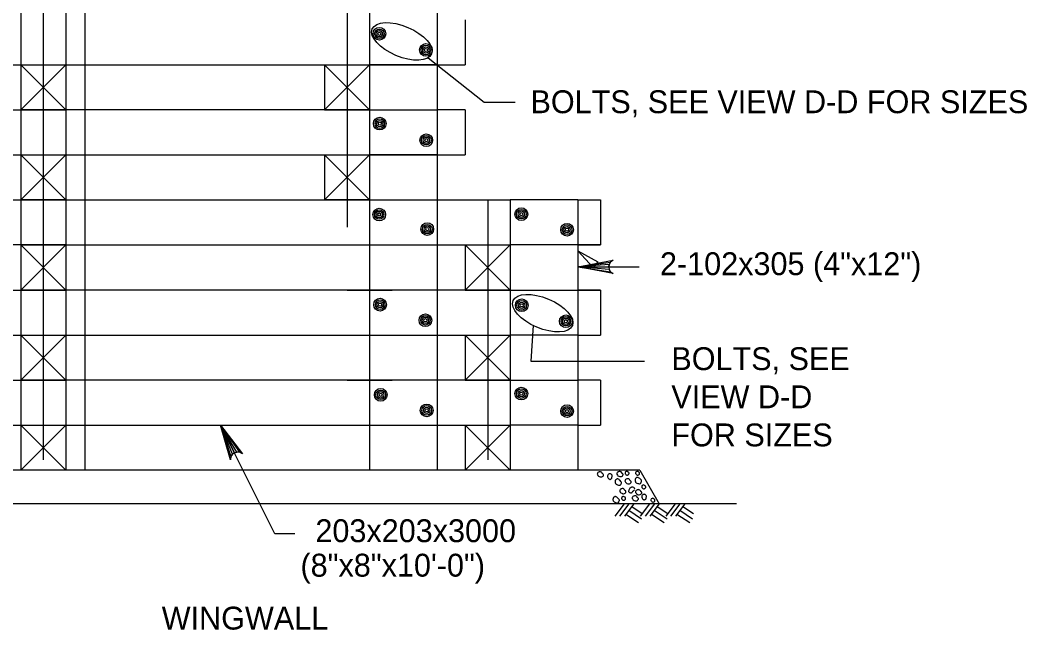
# Model space of a CAD drawing. Extents: x 638142 to 639291, y 297247 to 298438.
# Drawn here: x 638906.2 to 639038.3, y 297993.3 to 298073.2 of the extents above; entities that cross this region are included whole.
import ezdxf

# ---------------------------------------------------------------- set-up
doc = ezdxf.new("R2010")
doc.units = 0
doc.layers.add('3', color=7, linetype='Continuous')
doc.layers.add('5', color=7, linetype='Continuous')

msp = doc.modelspace()

# ---------------------------------------------------------------- linework, layer by layer
at = {"layer": '3'}
for p, q in [((638909.25, 298091), (638909.25, 298015.59)), ((638912.21, 298091), (638912.21, 298014.22)), ((638914.72, 298091), (638914.72, 298025.25)), ((638906.3, 298085.09), (638906.3, 298014.22)), ((638949.12, 298085.09), (638949.12, 298046.07)), ((638952.07, 298085.09), (638952.07, 298025.11)), ((638960.93, 298085.09), (638960.93, 298043.75)), ((638960.93, 298079.18), (638960.93, 298014.22)), ((638964.62, 298073.28), (638964.62, 298067.37)), ((638897.44, 298067.37), (638906.3, 298067.37)), ((638906.3, 298067.37), (638952.07, 298067.37)), ((638906.3, 298067.37), (638912.21, 298067.37)), ((638906.3, 298067.37), (638906.3, 298061.47)), ((638906.3, 298061.47), (638912.21, 298067.37)), ((638906.3, 298067.37), (638912.21, 298061.47)), ((638912.21, 298067.37), (638912.21, 298061.47)), ((638946.16, 298067.37), (638952.07, 298067.37)), ((638946.16, 298067.37), (638952.07, 298061.47)), ((638946.16, 298061.47), (638952.07, 298067.37)), ((638946.16, 298067.37), (638946.16, 298061.47)), ((638952.07, 298067.37), (638960.93, 298067.37)), ((638952.07, 298067.37), (638952.07, 298061.47)), ((638960.93, 298067.37), (638952.07, 298067.37)), ((638960.93, 298067.37), (638964.62, 298067.37)), ((638897.44, 298061.47), (638906.3, 298061.47)), ((638906.3, 298061.47), (638912.21, 298061.47)), ((638912.21, 298061.47), (638906.3, 298061.47)), ((638952.07, 298061.47), (638906.3, 298061.47)), ((638946.16, 298061.47), (638952.07, 298061.47)), ((638952.07, 298061.47), (638960.93, 298061.47)), ((638964.62, 298061.47), (638960.93, 298061.47)), ((638964.62, 298061.47), (638964.62, 298055.56)), ((638897.44, 298055.56), (638906.3, 298055.56)), ((638906.3, 298055.56), (638952.07, 298055.56)), ((638906.3, 298055.56), (638912.21, 298055.56)), ((638906.3, 298055.56), (638912.21, 298049.65)), ((638906.3, 298049.65), (638912.21, 298055.56)), ((638906.3, 298055.56), (638906.3, 298049.65)), ((638912.21, 298055.56), (638912.21, 298049.65)), ((638946.16, 298055.56), (638952.07, 298055.56)), ((638946.16, 298055.56), (638946.16, 298049.65)), ((638946.16, 298049.65), (638952.07, 298055.56)), ((638946.16, 298055.56), (638952.07, 298049.65)), ((638952.07, 298055.56), (638952.07, 298049.65)), ((638952.07, 298055.56), (638960.93, 298055.56)), ((638960.93, 298055.56), (638952.07, 298055.56)), ((638960.93, 298055.56), (638964.62, 298055.56)), ((638897.44, 298049.65), (638906.3, 298049.65)), ((638906.3, 298049.65), (638970.52, 298049.65)), ((638912.21, 298049.65), (638906.3, 298049.65)), ((638906.3, 298049.65), (638912.21, 298049.65)), ((638946.16, 298049.65), (638952.07, 298049.65)), ((638952.07, 298049.65), (638946.16, 298049.65)), ((638967.57, 298049.65), (638967.57, 298015.59)), ((638970.52, 298049.65), (638970.52, 298014.22)), ((638979.38, 298049.65), (638970.52, 298049.65)), ((638979.38, 298049.65), (638979.38, 298014.22)), ((638979.38, 298049.65), (638982.34, 298049.65)), ((638982.34, 298049.65), (638982.34, 298043.75)), ((638912.21, 298043.75), (638897.44, 298043.75)), ((638906.3, 298043.75), (638912.21, 298043.75)), ((638906.3, 298043.75), (638906.3, 298037.84)), ((638906.3, 298037.84), (638912.21, 298043.75)), ((638906.3, 298043.75), (638912.21, 298037.84)), ((638912.21, 298043.75), (638912.21, 298037.84)), ((638912.21, 298043.75), (638970.52, 298043.75)), ((638949.12, 298043.75), (638955.02, 298043.75)), ((638964.62, 298043.75), (638964.62, 298037.84)), ((638964.62, 298037.84), (638970.52, 298043.75)), ((638964.62, 298043.75), (638970.52, 298037.84)), ((638964.62, 298043.75), (638970.52, 298043.75)), ((638970.52, 298043.75), (638970.52, 298037.84)), ((638979.38, 298043.75), (638970.52, 298043.75)), ((638982.34, 298043.75), (638978.64, 298043.75)), ((638979.38, 298043.75), (638982.34, 298043.75)), ((638897.44, 298037.84), (638906.3, 298037.84)), ((638906.3, 298037.84), (638912.21, 298037.84)), ((638970.52, 298037.84), (638906.3, 298037.84)), ((638949.12, 298037.84), (638955.02, 298037.84)), ((638964.62, 298037.84), (638970.52, 298037.84)), ((638970.52, 298037.84), (638979.38, 298037.84)), ((638978.64, 298037.84), (638982.34, 298037.84)), ((638982.34, 298037.84), (638979.38, 298037.84)), ((638982.34, 298037.84), (638982.34, 298031.94)), ((638897.44, 298031.94), (638906.3, 298031.94)), ((638906.3, 298031.94), (638912.21, 298031.94)), ((638906.3, 298031.94), (638912.21, 298026.03)), ((638906.3, 298026.03), (638912.21, 298031.94)), ((638906.3, 298031.94), (638906.3, 298026.03)), ((638906.3, 298031.94), (638970.52, 298031.94)), ((638912.21, 298031.94), (638912.21, 298026.03)), ((638949.12, 298031.94), (638952.07, 298031.94)), ((638964.62, 298031.94), (638970.52, 298031.94)), ((638964.62, 298031.94), (638970.52, 298026.03)), ((638964.62, 298026.03), (638970.52, 298031.94)), ((638964.62, 298031.94), (638964.62, 298026.03)), ((638970.52, 298031.94), (638970.52, 298026.03)), ((638979.38, 298031.94), (638970.52, 298031.94)), ((638979.38, 298031.94), (638982.34, 298031.94)), ((638897.44, 298026.03), (638906.3, 298026.03)), ((638906.3, 298026.03), (638912.21, 298026.03)), ((638970.52, 298026.03), (638906.3, 298026.03)), ((638914.72, 298025.25), (638914.72, 298014.22)), ((638949.12, 298026.03), (638955.02, 298026.03)), ((638952.07, 298025.11), (638952.07, 298014.22)), ((638964.62, 298026.03), (638970.52, 298026.03)), ((638970.52, 298026.03), (638979.38, 298026.03)), ((638982.34, 298026.03), (638979.38, 298026.03)), ((638982.34, 298026.03), (638982.34, 298020.13)), ((638897.44, 298020.13), (638906.3, 298020.13)), ((638906.3, 298020.13), (638912.21, 298020.13)), ((638906.3, 298020.13), (638970.52, 298020.13)), ((638906.3, 298020.13), (638906.3, 298014.22)), ((638906.3, 298014.22), (638912.21, 298020.13)), ((638906.3, 298020.13), (638912.21, 298014.22)), ((638912.21, 298020.13), (638912.21, 298014.22)), ((638920.32, 298020.13), (638968.31, 298020.13)), ((638964.62, 298020.13), (638964.62, 298014.22)), ((638964.62, 298014.22), (638970.52, 298020.13)), ((638964.62, 298020.13), (638970.52, 298014.22)), ((638964.62, 298020.13), (638970.52, 298020.13)), ((638970.52, 298020.13), (638970.52, 298014.22)), ((638979.38, 298020.13), (638970.52, 298020.13)), ((638979.38, 298020.13), (638982.34, 298020.13)), ((638987.5, 298014.22), (638888.58, 298014.22)), ((638987.5, 298014.22), (638990.06, 298009.79)), ((639000.21, 298009.79), (638874.92, 298009.79)), ((638985.45, 298009.79), (638984.23, 298008.2)), ((638986.08, 298009.79), (638984.86, 298008.2)), ((638986.71, 298009.79), (638985.49, 298008.2)), ((638986.07, 298008.96), (638987.75, 298007.86)), ((638986.46, 298009.46), (638987.84, 298008.54)), ((638988.8, 298009.79), (638987.58, 298008.2)), ((638989.43, 298009.79), (638988.21, 298008.2)), ((638990.06, 298009.79), (638988.84, 298008.2)), ((638989.42, 298008.96), (638991.09, 298007.86)), ((638989.8, 298009.46), (638991.19, 298008.54)), ((638992.15, 298009.79), (638990.93, 298008.2)), ((638992.78, 298009.79), (638991.56, 298008.2)), ((638993.41, 298009.79), (638992.19, 298008.2)), ((638992.77, 298008.96), (638994.44, 298007.86)), ((638993.15, 298009.46), (638994.54, 298008.54)), ((638985.69, 298008.45), (638987.36, 298007.35)), ((638989.04, 298008.45), (638990.71, 298007.35)), ((638992.38, 298008.45), (638994.06, 298007.35))]:
    msp.add_line(p, q, dxfattribs=at)
for centre, radius in [((638953.35, 298071.44), 0.833), ((638953.35, 298071.44), 0.625), ((638953.35, 298071.44), 0.417), ((638953.35, 298071.44), 0.208), ((638959.45, 298069.32), 0.833), ((638959.45, 298069.32), 0.625), ((638959.45, 298069.32), 0.417), ((638959.45, 298069.32), 0.208), ((638953.4, 298059.66), 0.833), ((638953.4, 298059.66), 0.625), ((638953.4, 298059.66), 0.417), ((638953.4, 298059.66), 0.208), ((638959.5, 298057.49), 0.833), ((638959.5, 298057.49), 0.625), ((638959.5, 298057.49), 0.417), ((638959.5, 298057.49), 0.208), ((638953.32, 298047.74), 0.833), ((638971.97, 298047.79), 0.833), ((638953.32, 298047.74), 0.625), ((638953.32, 298047.74), 0.417), ((638953.32, 298047.74), 0.208), ((638971.97, 298047.79), 0.625), ((638971.97, 298047.79), 0.417), ((638971.97, 298047.79), 0.208), ((638959.63, 298045.83), 0.833), ((638959.63, 298045.83), 0.625), ((638959.63, 298045.83), 0.417), ((638959.63, 298045.83), 0.208), ((638977.97, 298045.75), 0.833), ((638977.97, 298045.75), 0.625), ((638977.97, 298045.75), 0.417), ((638977.97, 298045.75), 0.208), ((638953.44, 298035.92), 0.833), ((638972.02, 298035.84), 0.833), ((638953.44, 298035.92), 0.625), ((638953.44, 298035.92), 0.417), ((638953.44, 298035.92), 0.208), ((638972.02, 298035.84), 0.625), ((638972.02, 298035.84), 0.417), ((638972.02, 298035.84), 0.208), ((638959.39, 298033.88), 0.833), ((638959.39, 298033.88), 0.625), ((638959.39, 298033.88), 0.417), ((638959.39, 298033.88), 0.208), ((638977.81, 298033.75), 0.833), ((638977.81, 298033.75), 0.625), ((638977.81, 298033.75), 0.417), ((638977.81, 298033.75), 0.208), ((638953.52, 298024.1), 0.833), ((638971.97, 298024.26), 0.833), ((638971.97, 298024.26), 0.625), ((638953.52, 298024.1), 0.625), ((638953.52, 298024.1), 0.417), ((638953.52, 298024.1), 0.208), ((638971.97, 298024.26), 0.417), ((638971.97, 298024.26), 0.208), ((638959.55, 298022.06), 0.833), ((638959.55, 298022.06), 0.625), ((638959.55, 298022.06), 0.417), ((638959.55, 298022.06), 0.208), ((638977.97, 298021.96), 0.833), ((638977.97, 298021.96), 0.625), ((638977.97, 298021.96), 0.417), ((638977.97, 298021.96), 0.208)]:
    msp.add_circle(centre, radius, dxfattribs=at)
for centre, radius, start, end in [((638982.12, 298013.72), 0.185, 160.92, 203.6312), ((638982.22, 298013.68), 0.289, 132.2712, 160.92), ((638982.45, 298013.86), 0.547, 203.6312, 228.0682), ((638982.28, 298013.61), 0.383, 107.4489, 132.2712), ((638982.43, 298013.83), 0.508, 228.0682, 257.7363), ((638982.3, 298013.55), 0.454, 90, 107.449), ((638982.3, 298013.61), 0.387, 71.0851, 90), ((638982.4, 298013.73), 0.402, 257.7363, 291.1829), ((638982.35, 298013.75), 0.246, 39.2919, 71.0851), ((638982.27, 298013.68), 0.35, 12.7289, 39.2919), ((638982.39, 298013.76), 0.433, 291.1829, 314.9975), ((638982.53, 298013.56), 0.227, 36.0298, 75.5915), ((638982.57, 298013.58), 0.181, 314.9975, 352.2416), ((638982.57, 298013.58), 0.187, 352.2416, 36.0298), ((638983.63, 298013.41), 0.347, 162.0407, 192.5299), ((638983.58, 298013.42), 0.303, 134.9975, 162.0407), ((638983.69, 298013.43), 0.418, 192.5299, 220.2507), ((638983.61, 298013.4), 0.343, 109.6149, 134.9975), ((638983.8, 298013.51), 0.555, 220.2507, 239.7458), ((638983.59, 298013.45), 0.286, 75.9649, 109.6149), ((638983.6, 298013.17), 0.155, 239.7458, 277.0923), ((638983.59, 298013.27), 0.256, 277.0923, 293.1968), ((638983.58, 298013.4), 0.338, 45.0971, 75.9649), ((638983.55, 298013.35), 0.343, 293.1968, 307.0979), ((638983.61, 298013.27), 0.244, 307.0979, 330.9432), ((638983.63, 298013.45), 0.265, 6.7104, 45.0971), ((638983.57, 298013.29), 0.292, 330.9432, 352.744), ((638983.59, 298013.44), 0.311, 331.3493, 6.7104), ((638984.76, 298012.71), 0.498, 161.5635, 177.6608), ((638984.63, 298012.75), 0.357, 142.5289, 161.5635), ((638984.56, 298012.8), 0.273, 111.0358, 142.5289), ((638984.56, 298012.82), 0.256, 78.5014, 111.0358), ((638984.68, 298013.75), 0.185, 160.92, 203.6312), ((638984.78, 298013.72), 0.289, 132.2712, 160.92), ((638985.01, 298013.9), 0.547, 203.6312, 228.0682), ((638984.84, 298013.65), 0.383, 107.4489, 132.2712), ((638984.54, 298012.72), 0.358, 61.7014, 78.5014), ((638984.99, 298013.87), 0.508, 228.0682, 257.7363), ((638984.12, 298011.95), 1.23, 52.6686, 61.7014), ((638984.87, 298013.58), 0.454, 90, 107.449), ((638984.87, 298013.65), 0.387, 71.0851, 90), ((638984.26, 298012.13), 1, 38.6623, 52.6686), ((638984.97, 298013.77), 0.402, 257.7363, 291.1829), ((638984.91, 298013.78), 0.246, 39.2919, 71.0851), ((638984.83, 298013.72), 0.35, 12.7289, 39.2919), ((638984.96, 298013.8), 0.433, 291.1829, 314.9975), ((638985.1, 298013.6), 0.227, 36.0298, 75.5915), ((638985.13, 298013.62), 0.181, 314.9975, 352.2416), ((638985.13, 298013.62), 0.187, 352.2416, 36.0298), ((638985.75, 298012.81), 0.185, 160.92, 203.6312), ((638985.79, 298013.84), 0.212, 153.4329, 176.3744), ((638985.82, 298013.84), 0.243, 176.3744, 204.4459), ((638985.85, 298012.77), 0.289, 132.2712, 160.92), ((638985.86, 298013.81), 0.29, 133.8613, 153.4329), ((638985.87, 298013.86), 0.303, 204.4459, 229.5269), ((638985.79, 298013.87), 0.198, 82.8756, 133.8613), ((638985.91, 298012.71), 0.383, 107.4489, 132.2712), ((638985.84, 298013.83), 0.259, 229.5269, 261.8706), ((638985.93, 298012.64), 0.454, 90, 107.449), ((638985.85, 298013.86), 0.285, 261.8706, 292.6593), ((638985.79, 298013.84), 0.234, 36.1405, 82.8756), ((638985.93, 298012.7), 0.387, 71.0851, 90), ((638985.89, 298013.78), 0.218, 33.6924, 77.7435), ((638985.86, 298013.82), 0.247, 292.6593, 318.8116), ((638985.87, 298013.81), 0.229, 318.8116, 345.9971), ((638985.98, 298012.84), 0.246, 39.2919, 71.0851), ((638985.92, 298013.8), 0.187, 345.9971, 33.6924), ((638985.9, 298012.77), 0.35, 12.7289, 39.2919), ((638986.16, 298012.65), 0.227, 36.0298, 75.5915), ((638987.4, 298012.91), 0.498, 161.5635, 177.6608), ((638987.48, 298012.91), 0.579, 177.6608, 192.9957), ((638987.27, 298012.95), 0.357, 142.5289, 161.5635), ((638987.17, 298013.84), 0.212, 153.4329, 176.3744), ((638987.21, 298013.84), 0.243, 176.3744, 204.4459), ((638987.24, 298013.81), 0.29, 133.8613, 153.4329), ((638987.26, 298013.86), 0.303, 204.4459, 229.5269), ((638987.2, 298013.01), 0.273, 111.0358, 142.5289), ((638987.18, 298013.87), 0.198, 82.8756, 133.8613), ((638987.23, 298013.83), 0.259, 229.5269, 261.8706), ((638987.19, 298013.02), 0.256, 78.5014, 111.0358), ((638987.23, 298013.86), 0.285, 261.8706, 292.6593), ((638987.18, 298013.84), 0.234, 36.1405, 82.8756), ((638987.17, 298012.92), 0.358, 61.7014, 78.5014), ((638987.28, 298013.78), 0.218, 33.6924, 77.7435), ((638987.25, 298013.82), 0.247, 292.6593, 318.8116), ((638986.76, 298012.15), 1.23, 52.6686, 61.7014), ((638987.26, 298013.81), 0.229, 318.8116, 345.9971), ((638987.3, 298013.8), 0.187, 345.9971, 33.6924), ((638986.9, 298012.33), 1, 38.6623, 52.6686), ((638987.4, 298012.73), 0.361, 15.2216, 38.6623), ((638984.85, 298012.7), 0.579, 177.6608, 192.9957), ((638984.61, 298012.65), 0.333, 192.9957, 213.2749), ((638984.57, 298012.63), 0.294, 213.2749, 237.2671), ((638984.91, 298013.16), 0.926, 237.2671, 250.7161), ((638984.87, 298013.04), 0.798, 250.7161, 266.6338), ((638984.84, 298012.51), 0.266, 266.6338, 294.3814), ((638985.06, 298011.52), 0.185, 160.92, 203.6312), ((638985.16, 298011.49), 0.289, 132.2712, 160.92), ((638984.89, 298012.39), 0.138, 294.3814, 320.1919), ((638985.23, 298011.42), 0.383, 107.4489, 132.2712), ((638984.73, 298012.53), 0.348, 320.1919, 336.3613), ((638984.76, 298012.7), 0.382, 310.4771, 334.6604), ((638984.76, 298012.53), 0.361, 15.2216, 38.6623), ((638984.98, 298012.59), 0.14, 334.6604, 15.2216), ((638985.25, 298011.35), 0.454, 90, 107.449), ((638985.25, 298011.42), 0.387, 71.0851, 90), ((638985.29, 298011.55), 0.246, 39.2919, 71.0851), ((638985.21, 298011.48), 0.35, 12.7289, 39.2919), ((638985.48, 298011.36), 0.227, 36.0298, 75.5915), ((638986.08, 298012.95), 0.547, 203.6312, 228.0682), ((638986.05, 298012.93), 0.508, 228.0682, 257.7363), ((638986.03, 298012.82), 0.402, 257.7363, 291.1829), ((638986.52, 298011.46), 0.468, 159.491, 180), ((638986.69, 298011.39), 0.652, 144.4599, 159.491), ((638986.74, 298011.36), 0.712, 130.0785, 144.4599), ((638986.02, 298012.85), 0.433, 291.1829, 314.9975), ((638986.54, 298011.6), 0.398, 114.4421, 130.0785), ((638986.2, 298012.67), 0.181, 314.9975, 352.2416), ((638986.19, 298012.67), 0.187, 352.2416, 36.0298), ((638986.63, 298011.39), 0.632, 102.0363, 114.4421), ((638986.55, 298011.76), 0.252, 50.53, 102.0363), ((638987.69, 298010.58), 1.38, 134.9975, 140.4906), ((638986.48, 298011.67), 0.366, 8.2706, 50.53), ((638988.01, 298010.26), 1.83, 130.2337, 134.9975), ((638987.24, 298012.85), 0.333, 192.9957, 213.2749), ((638987.21, 298012.83), 0.294, 213.2749, 237.2671), ((638987.24, 298011.35), 0.289, 132.2712, 160.92), ((638987.3, 298011.28), 0.383, 107.4489, 132.2712), ((638987.55, 298013.36), 0.926, 237.2671, 250.7161), ((638987.32, 298011.21), 0.454, 90, 107.449), ((638987.51, 298013.24), 0.798, 250.7161, 266.6338), ((638987.32, 298011.28), 0.387, 71.0851, 90), ((638987.37, 298011.41), 0.246, 39.2919, 71.0851), ((638987.48, 298012.71), 0.266, 266.6338, 294.3814), ((638987.29, 298011.34), 0.35, 12.7289, 39.2919), ((638987.53, 298012.59), 0.138, 294.3814, 320.1919), ((638987.39, 298012.9), 0.382, 310.4771, 334.6604), ((638987.37, 298012.73), 0.348, 320.1919, 336.3613), ((638987.61, 298012.79), 0.14, 334.6604, 15.2216), ((638987.98, 298012.05), 0.212, 153.4329, 176.3744), ((638988.01, 298012.05), 0.243, 176.3744, 204.4459), ((638988.05, 298012.02), 0.29, 133.8613, 153.4329), ((638988.06, 298012.07), 0.303, 204.4459, 229.5269), ((638987.99, 298012.08), 0.198, 82.8756, 133.8613), ((638988.04, 298012.04), 0.259, 229.5269, 261.8706), ((638988.04, 298012.07), 0.285, 261.8706, 292.6593), ((638987.98, 298012.05), 0.234, 36.1405, 82.8756), ((638988.08, 298011.99), 0.218, 33.6924, 77.7435), ((638988.05, 298012.03), 0.247, 292.6593, 318.8116), ((638988.07, 298012.02), 0.229, 318.8116, 345.9971), ((638988.11, 298012.01), 0.187, 345.9971, 33.6924), ((638984.49, 298010.39), 0.498, 161.5635, 177.6608), ((638984.57, 298010.38), 0.579, 177.6608, 192.9957), ((638984.33, 298010.33), 0.333, 192.9957, 213.2749), ((638984.36, 298010.43), 0.357, 142.5289, 161.5635), ((638984.29, 298010.48), 0.273, 111.0358, 142.5289), ((638984.28, 298010.5), 0.256, 78.5014, 111.0358), ((638984.26, 298010.4), 0.358, 61.7014, 78.5014), ((638983.85, 298009.63), 1.23, 52.6686, 61.7014), ((638983.99, 298009.81), 1, 38.6623, 52.6686), ((638984.48, 298010.37), 0.382, 310.4771, 334.6604), ((638984.49, 298010.21), 0.361, 15.2216, 38.6623), ((638984.7, 298010.27), 0.14, 334.6604, 15.2216), ((638985.4, 298011.67), 0.547, 203.6312, 228.0682), ((638985.37, 298011.64), 0.508, 228.0682, 257.7363), ((638985.34, 298010.54), 0.212, 153.4329, 176.3744), ((638985.37, 298010.54), 0.243, 176.3744, 204.4459), ((638985.41, 298010.51), 0.29, 133.8613, 153.4329), ((638985.43, 298010.57), 0.303, 204.4459, 229.5269), ((638985.35, 298010.57), 0.198, 82.8756, 133.8613), ((638985.4, 298010.53), 0.259, 229.5269, 261.8706), ((638985.35, 298011.53), 0.402, 257.7363, 291.1829), ((638985.4, 298010.56), 0.285, 261.8706, 292.6593), ((638985.35, 298010.54), 0.234, 36.1405, 82.8756), ((638985.34, 298011.56), 0.433, 291.1829, 314.9975), ((638985.45, 298010.48), 0.218, 33.6924, 77.7435), ((638985.42, 298010.52), 0.247, 292.6593, 318.8116), ((638985.43, 298010.51), 0.229, 318.8116, 345.9971), ((638985.47, 298010.5), 0.187, 345.9971, 33.6924), ((638985.52, 298011.39), 0.181, 314.9975, 352.2416), ((638985.51, 298011.39), 0.187, 352.2416, 36.0298), ((638986.22, 298011.46), 0.175, 180, 213.8235), ((638986.23, 298011.47), 0.188, 213.8235, 243.437), ((638986.31, 298011.63), 0.368, 243.437, 264.4731), ((638986.33, 298011.83), 0.576, 264.4731, 280.304), ((638986.42, 298011.38), 0.116, 280.304, 316.0526), ((638986.22, 298011.57), 0.384, 316.0526, 327.4482), ((638986.69, 298010.58), 0.185, 160.92, 203.6312), ((638986.79, 298010.54), 0.289, 132.2712, 160.92), ((638987.03, 298010.72), 0.547, 203.6312, 228.0682), ((638987.41, 298010.81), 1.03, 140.4906, 147.4482), ((638986.86, 298010.47), 0.383, 107.4489, 132.2712), ((638987, 298010.69), 0.508, 228.0682, 257.7363), ((638986.88, 298010.4), 0.454, 90, 107.449), ((638986.88, 298010.47), 0.387, 71.0851, 90), ((638986.98, 298010.59), 0.402, 257.7363, 291.1829), ((638987.14, 298011.38), 0.185, 160.92, 203.6312), ((638987.47, 298011.53), 0.547, 203.6312, 228.0682), ((638986.92, 298010.61), 0.246, 39.2919, 71.0851), ((638987.44, 298011.5), 0.508, 228.0682, 257.7363), ((638986.84, 298010.54), 0.35, 12.7289, 39.2919), ((638986.97, 298010.62), 0.433, 291.1829, 314.9975), ((638987.11, 298010.42), 0.227, 36.0298, 75.5915), ((638987.15, 298010.44), 0.181, 314.9975, 352.2416), ((638987.14, 298010.44), 0.187, 352.2416, 36.0298), ((638987.42, 298011.39), 0.402, 257.7363, 291.1829), ((638987.41, 298011.42), 0.433, 291.1829, 314.9975), ((638987.55, 298011.22), 0.227, 36.0298, 75.5915), ((638987.59, 298011.24), 0.181, 314.9975, 352.2416), ((638987.58, 298011.25), 0.187, 352.2416, 36.0298), ((638988.12, 298010.73), 0.347, 162.0407, 192.5299), ((638988.19, 298010.75), 0.418, 192.5299, 220.2507), ((638988.08, 298010.74), 0.303, 134.9975, 162.0407), ((638988.1, 298010.72), 0.343, 109.6149, 134.9975), ((638988.29, 298010.83), 0.555, 220.2507, 239.7458), ((638988.08, 298010.77), 0.286, 75.9649, 109.6149), ((638988.09, 298010.49), 0.155, 239.7458, 277.0923), ((638988.08, 298010.59), 0.256, 277.0923, 293.1968), ((638988.07, 298010.72), 0.338, 45.0971, 75.9649), ((638988.04, 298010.67), 0.343, 293.1968, 307.0979), ((638988.1, 298010.59), 0.244, 307.0979, 330.9432), ((638988.12, 298010.77), 0.265, 6.7104, 45.0971), ((638988.06, 298010.61), 0.292, 330.9432, 352.744), ((638988.08, 298010.77), 0.311, 331.3493, 6.7104), ((638989.19, 298010.3), 0.212, 153.4329, 176.3744), ((638989.22, 298010.3), 0.243, 176.3744, 204.4459), ((638989.26, 298010.27), 0.29, 133.8613, 153.4329), ((638989.27, 298010.32), 0.303, 204.4459, 229.5269), ((638989.19, 298010.33), 0.198, 82.8756, 133.8613), ((638989.19, 298010.3), 0.234, 36.1405, 82.8756), ((638989.29, 298010.24), 0.218, 33.6924, 77.7435), ((638989.27, 298010.27), 0.229, 318.8116, 345.9971), ((638989.32, 298010.26), 0.187, 345.9971, 33.6924), ((638984.3, 298010.31), 0.294, 213.2749, 237.2671), ((638984.64, 298010.84), 0.926, 237.2671, 250.7161), ((638984.6, 298010.72), 0.798, 250.7161, 266.6338), ((638984.57, 298010.19), 0.266, 266.6338, 294.3814), ((638984.62, 298010.07), 0.138, 294.3814, 320.1919), ((638984.46, 298010.2), 0.348, 320.1919, 336.3613), ((638989.24, 298010.29), 0.259, 229.5269, 261.8706), ((638989.25, 298010.32), 0.285, 261.8706, 292.6593), ((638989.26, 298010.28), 0.247, 292.6593, 318.8116)]:
    msp.add_arc(centre, radius, start, end, dxfattribs=at)
at = {"layer": '5'}
for p, q in [((638959.76, 298068.3), (638967.11, 298062.46)), ((638967.11, 298062.46), (638971.15, 298062.46)), ((638939.64, 298005.86), (638932.51, 298020.13)), ((638942.26, 298005.86), (638939.64, 298005.86))]:
    msp.add_line(p, q, dxfattribs=at)
msp.add_lwpolyline([(638981.99, 298041.55), (638981.38, 298040.78), (638979.37, 298043)], close=True, dxfattribs=at)
for points in [[(638979.38, 298040.87), (638984.04, 298041.74), (638983.68, 298041.49), (638983.5, 298041.18), (638983.45, 298040.87), (638983.5, 298040.55), (638983.68, 298040.24), (638984.04, 298039.99), (638979.38, 298040.87), (638983.68, 298040.24), (638983.5, 298040.55), (638979.38, 298040.87), (638983.45, 298040.87), (638983.5, 298041.18), (638979.38, 298040.87), (638983.68, 298041.49)], [(638979.38, 298040.87), (638987.43, 298040.87)], [(638973.53, 298033.19), (638973.2, 298028.5), (638988.13, 298028.5)], [(638932.51, 298020.13), (638935.38, 298016.35), (638934.99, 298016.56), (638934.63, 298016.58), (638934.33, 298016.49), (638934.07, 298016.3), (638933.87, 298016), (638933.81, 298015.57), (638932.51, 298020.13), (638933.87, 298016), (638934.07, 298016.3), (638932.51, 298020.13), (638934.33, 298016.49), (638934.63, 298016.58), (638932.51, 298020.13), (638934.99, 298016.56)]]:
    msp.add_lwpolyline(points, dxfattribs=at)
for centre in [(638956.3, 298070.44), (638974.78, 298034.81)]:
    msp.add_ellipse(centre, major_axis=(-3.89, 1.64), ratio=0.473013, dxfattribs=at)

# ---------------------------------------------------------------- texts
for s, height, p in [('BOLTS, SEE VIEW D-D FOR SIZES', 3.0001, (638973.17, 298061.03)), ('2-102x305 (4"x12")', 3.0001, (638990.16, 298039.79)), ('BOLTS, SEE', 3, (638991.65, 298027.34)), ('VIEW D-D', 3, (638991.65, 298022.34)), ('FOR SIZES', 3, (638991.65, 298017.34)), ('203x203x3000', 3.0001, (638944.95, 298004.78)), ('(8"x8"x10\'-0")', 3.0001, (638942.99, 298000.26)), ('WINGWALL', 3, (638924.79, 297993.32))]:
    msp.add_text(s, height=height, dxfattribs=at).set_placement(p)

doc.saveas('drawing.dxf')
